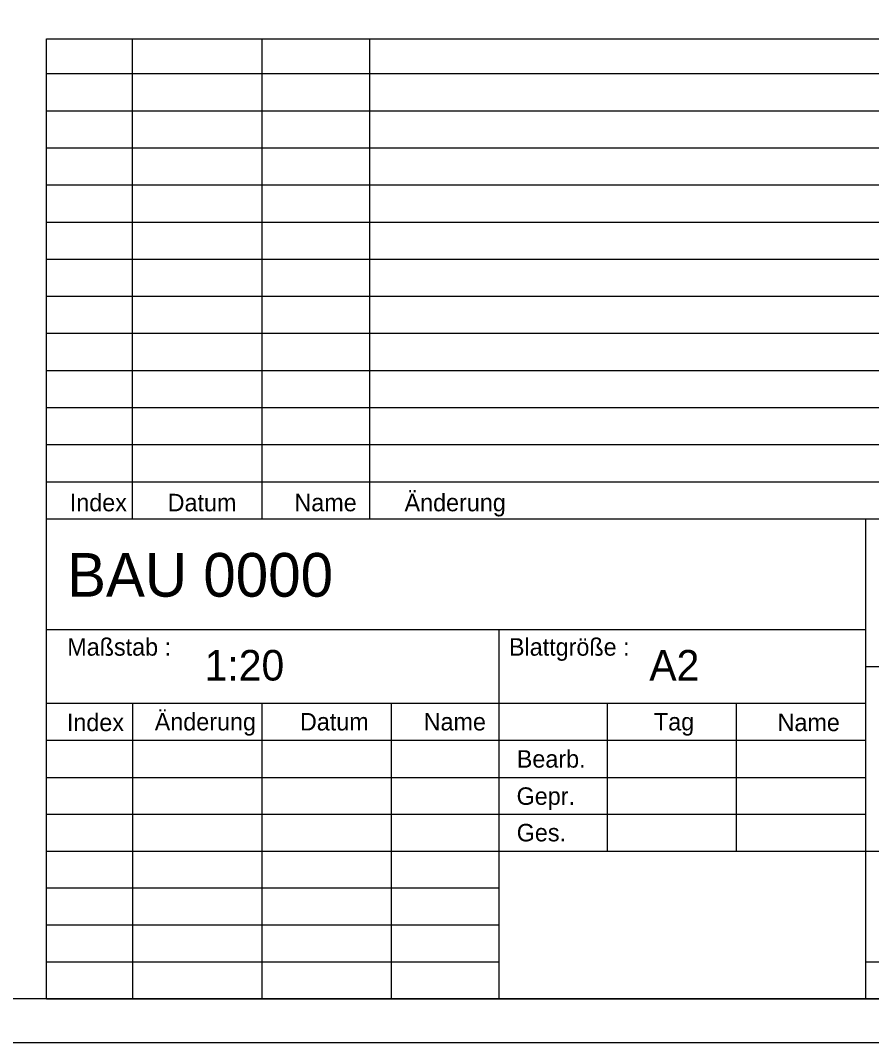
# Model space of a CAD drawing. Extents: x 0 to 11.9, y 0 to 8.4.
# Drawn here: x 8.163 to 10.113, y 0 to 2.342 of the extents above; entities that cross this region are included whole.
import ezdxf

# ---------------------------------------------------------------- set-up
doc = ezdxf.new("R2010")
doc.units = 0
doc.layers.add('90_Plankopf', color=7, linetype='Continuous')

msp = doc.modelspace()

# ---------------------------------------------------------------- linework, layer by layer
at = {"layer": '90_Plankopf'}
for p, q in [((8.2224, 1.1998), (8.2224, 2.2996)), ((8.2224, 2.2996), (11.78, 2.2996)), ((8.42, 1.1998), (8.42, 2.2996)), ((8.7165, 1.1998), (8.7165, 2.2996)), ((8.9636, 1.1998), (8.9636, 2.2996)), ((8.2224, 2.2198), (11.78, 2.2198)), ((8.2224, 2.1348), (11.78, 2.1348)), ((8.2224, 2.0498), (11.78, 2.0498)), ((8.2224, 1.9648), (11.78, 1.9648)), ((8.2224, 1.8798), (11.78, 1.8798)), ((8.2224, 1.7948), (11.78, 1.7948)), ((8.2224, 1.7098), (11.78, 1.7098)), ((8.2224, 1.6248), (11.78, 1.6248)), ((8.2224, 1.5398), (11.78, 1.5398)), ((8.2224, 1.4548), (11.78, 1.4548)), ((8.2224, 1.3698), (11.78, 1.3698)), ((8.2224, 1.2848), (11.78, 1.2848)), ((8.2224, 1.1998), (11.78, 1.1998)), ((8.2224, 0.1), (8.2224, 1.1998)), ((8.2224, 1.1998), (11.78, 1.1998)), ((10.1, 0.1), (10.1, 1.1998)), ((8.2224, 0.946), (10.1, 0.946)), ((9.26, 0.1), (9.26, 0.946)), ((10.1, 0.8614), (11.78, 0.8614)), ((8.2224, 0.7774), (10.1, 0.7774)), ((8.42, 0.7768), (8.42, 0.1)), ((8.7165, 0.1), (8.7165, 0.7768)), ((9.013, 0.1), (9.013, 0.7768)), ((9.5071, 0.7768), (9.5071, 0.4384)), ((9.8036, 0.4384), (9.8036, 0.7768)), ((8.2224, 0.6926), (10.1, 0.6926)), ((8.2224, 0.6076), (10.1, 0.6076)), ((8.2224, 0.523), (10.1, 0.523)), ((8.2224, 0.4384), (10.1, 0.4384)), ((8.2224, 0.4384), (10.1, 0.4384)), ((9.26, 0.4384), (10.1, 0.4384)), ((10.1, 0.4384), (11.78, 0.4384)), ((9.26, 0.3538), (8.2224, 0.3538)), ((9.26, 0.2692), (8.2224, 0.2692)), ((8.2224, 0.1846), (9.26, 0.1846)), ((10.1, 0.1846), (11.78, 0.1846)), ((11.78, 0.1), (8.2224, 0.1)), ((8.2224, 0.1), (9.26, 0.1)), ((8.456, 0.1), (11.78, 0.1)), ((8.456, 0.1), (11.78, 0.1))]:
    msp.add_line(p, q, dxfattribs=at)
for points in [[(0, 0), (11.88, 0), (11.88, 8.4), (0, 8.4)], [(0.5, 8.3), (11.78, 8.3), (11.78, 0.1), (0.5, 0.1)]]:
    msp.add_lwpolyline(points, close=True, dxfattribs=at)

# ---------------------------------------------------------------- texts
for s, height, p in [('Änderung', 0.04, (9.0431, 1.2171)), ('Index', 0.04, (8.2761, 1.2171)), ('Datum', 0.04, (8.5003, 1.2171)), ('Name', 0.04, (8.7908, 1.2171)), ('BAU 0000      ', 0.1, (8.2698, 1.0215)), ('Maßstab :', 0.04, (8.2703, 0.8863)), ('Blattgröße :', 0.039998, (9.2823, 0.8863)), ('1:20     ', 0.07, (8.5852, 0.8294)), ('A2       ', 0.07, (9.604, 0.8294)), ('Index', 0.04, (8.2694, 0.7135)), ('Änderung', 0.04, (8.4707, 0.715)), ('Datum', 0.04, (8.8034, 0.715)), ('Name', 0.04, (9.0869, 0.715)), ('Tag', 0.04, (9.6145, 0.715)), ('Name', 0.04, (9.8978, 0.7135)), ('Bearb.', 0.04, (9.3003, 0.6298)), ('Gepr.', 0.04, (9.2998, 0.5446)), ('Ges.', 0.04, (9.3001, 0.4609))]:
    msp.add_text(s, height=height, dxfattribs=at).set_placement(p)

doc.saveas('drawing.dxf')
